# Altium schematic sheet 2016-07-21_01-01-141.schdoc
size 313 x 134 mm; SheetNumber: 1; SheetTotal: 1
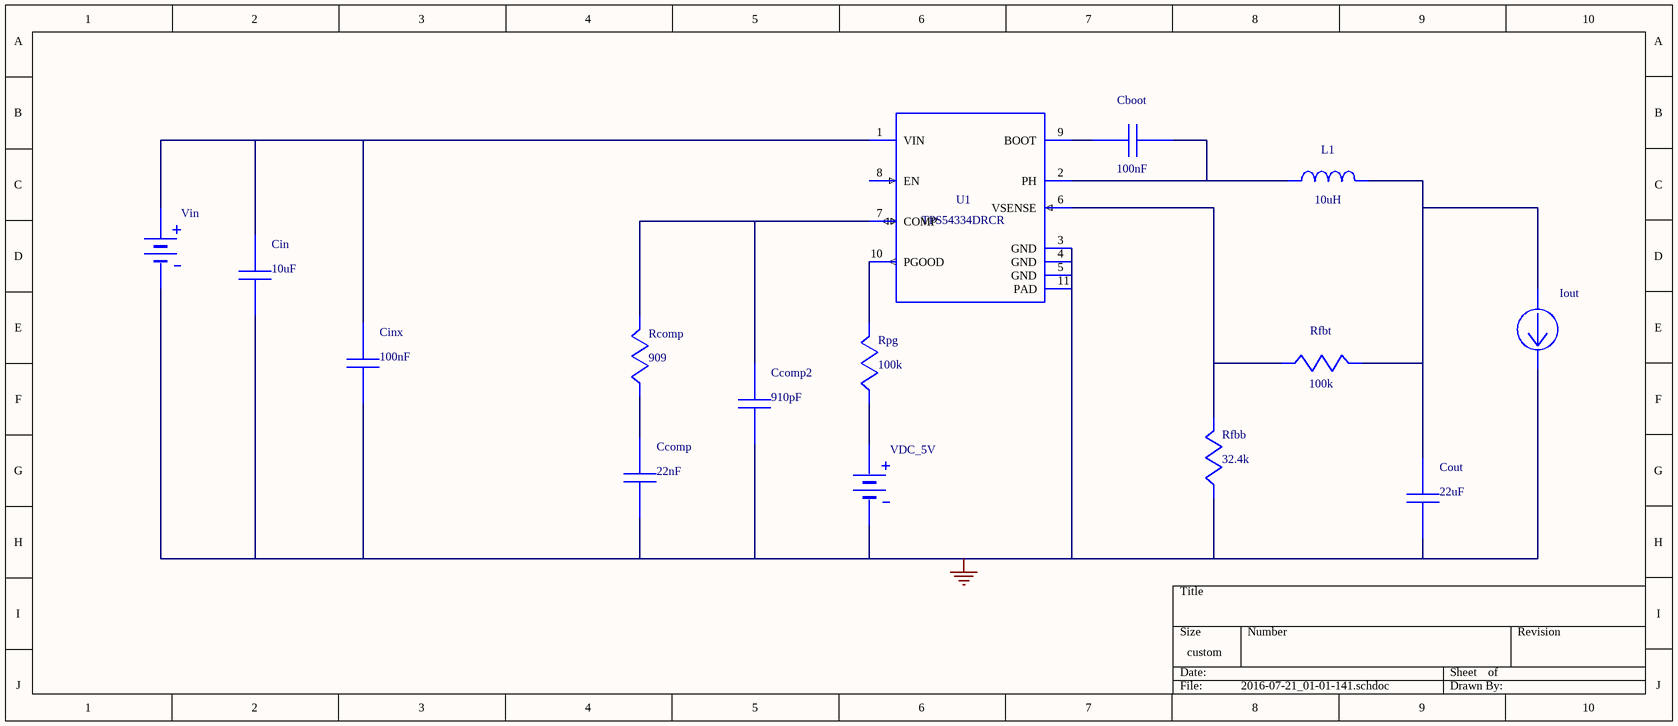
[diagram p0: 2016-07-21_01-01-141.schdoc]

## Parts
Cboot  value 100nF  (hidden comment: C0805C104K5RACTU)
Ccomp  value 22nF  (hidden comment: CC0805KRX7R9BB223)
Ccomp2  value 910pF  (hidden comment: CL21C911JBCNNNC)
Cin  value 10uF  (hidden comment: GRM31CR61E106KA12L)
Cinx  value 100nF  (hidden comment: C0805C104K5RACTU)
Cout  value 22uF  (hidden comment: GRM21BR60J226ME39L)
Iout  WB_CURRENT_LOAD  (value not drawn)
L1  value 10uH  (hidden comment: SRU1038-100Y)
Rcomp  value 909  (hidden comment: CRCW0402909RFKED)
Rfbb  value 32.4k  (hidden comment: CRCW040232K4FKED)
Rfbt  value 100k  (hidden comment: CRCW0402100KFKED)
Rpg  value 100k  (hidden comment: CRCW0402100KFKED)
U1  TPS54334DRCR
VDC_5V  WB_PRIM_DC_VOLTAGE_SOURCE  (value not drawn)
Vin  WB_BATTERY  (value not drawn)

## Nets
0: Ccomp.2 Ccomp2.2 Cin.2 Cinx.2 Cout.2 Iout.2(-) Rfbb.2 U1.3(GND) U1.4(GND) U1.5(GND) U1.11(PAD) VDC_5V.2(-) Vin.2(-)
NetCboot_1: Cboot.1 U1.9(BOOT)
NetCboot_2: Cboot.2 L1.1 U1.2(PH)
NetCcomp2_1: Ccomp2.1 Rcomp.1 U1.7(COMP)
NetCcomp_1: Ccomp.1 Rcomp.2
NetCin_1: Cin.1 Cinx.1 U1.1(VIN) Vin.1(+)
NetCout_1: Cout.1 Iout.1(+) L1.2 Rfbt.1
NetRfbb_1: Rfbb.1 Rfbt.2 U1.6(VSENSE)
NetRpg_1: Rpg.1 U1.10(PGOOD)
NetRpg_2: Rpg.2 VDC_5V.1(+)

Not connected (* = marked no-connect by the designer): U1 8(EN)

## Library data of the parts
Cboot Cinx = C0805C104K5RACTU: Manufacturer Name: Kemet
Ccomp = CC0805KRX7R9BB223: CC0805KRX7R9BB22; Manufacturer Name: Yageo America
Ccomp2 = CL21C911JBCNNNC: Manufacturer Name: Samsung Electro-Mechanics
Cin = GRM31CR61E106KA12L: GRM31CR61E106KA1; Manufacturer Name: MuRata
Cout = GRM21BR60J226ME39L: GRM21BR60J226ME3; Manufacturer Name: MuRata
L1 = SRU1038-100Y: Manufacturer Name: Bourns
Rcomp = CRCW0402909RFKED: Manufacturer Name: Vishay-Dale
Rfbb = CRCW040232K4FKED: Manufacturer Name: Vishay-Dale
Rfbt Rpg = CRCW0402100KFKED: Manufacturer Name: Vishay-Dale
U1 = TPS54334DRCR: Manufacturer Name: Texas Instruments
VDC_5V = WB_PRIM_DC_VOLTAGE_SOURCE: WB_PRIM_DC_VOLTA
